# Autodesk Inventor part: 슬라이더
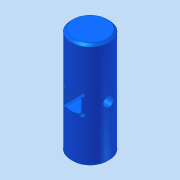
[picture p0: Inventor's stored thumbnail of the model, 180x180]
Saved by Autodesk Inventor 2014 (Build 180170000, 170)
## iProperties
Company: 한국ATC센터
Created: 2015-04
Part Number: 슬라이더
Document SubType Name: Modeling
Designer: KYOUNG IL JANG
Density: 1 g/cm^3
Material: 일반
Mass: 11.2119 g
Surface Area: 38.892 cm^2
Volume: 11.2119 cm^3
Appearance: 청록색
Author: KYOUNG IL JANG
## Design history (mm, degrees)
sketch "스케치1"
  geometry: C1 r 9 at (0, 0); 1 further point
  constraints: 1 centre point, 1 coincident
  dimensions: "d0" = 18 diameter of C1
extrude "돌출1" new body sketch "스케치1" stored distance "d1" = 50; taper "d2" = 0 deg
node "작업 평면1"
sketch "스케치3"
  geometry: L1 (4, 25)-(-4, 25); L2 (-4, 25)-(-4, -25); L3 (-4, -25)-(4, -25); L4 (4, -25)-(4, 25); 3 further points
  constraints: 8 end point, 2 midpoint, 2 parallel, 1 horizontal, 1 horizontal alignment, 1 perpendicular, 1 vertical alignment
  dimensions: "d5" = 8 distance of L1.start L1.end; "d6" = 50 distance of L1.end L2.end
extrude "돌출3" cut sketch "스케치3" stored distance "d7" = 8; taper "d8" = 0 deg
sketch "스케치4"
  geometry: 5 further points
hole "구멍1" sketch "스케치4" at (4, 4), (-4, 4), (-4, -4), (4, -4) diameter "d9" = 2; stored, may be unused: countersink angle "d13" = 90 deg, drill point angle "d15" = 118 deg; dims "d10" = 6, "d11" = 4, "d12" = 2, "d14" = 8
node "작업 평면2"
sketch "스케치5"
  geometry: 1 further point
hole "구멍2" sketch "스케치5" at (0, 0) diameter "d16" = 5; stored, may be unused: countersink angle "d20" = 90 deg, drill point angle "d22" = 118 deg; dims "d17" = 6, "d18" = 4, "d19" = 2, "d21" = 8
chamfer "모따기1" distance "d23" = 1; stored, may be unused: second distance "d24" = 2, angle "d25" = 45 deg
node "솔리드1"
mirror "대칭1"
